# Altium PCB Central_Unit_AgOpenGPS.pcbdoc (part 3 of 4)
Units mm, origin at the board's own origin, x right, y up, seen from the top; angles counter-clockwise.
Board outline 200.19 x 122.57 mm, 2 copper layers (Top Layer, Bottom Layer); 271 components, 213 nets, 1023 pads, 412 vias.
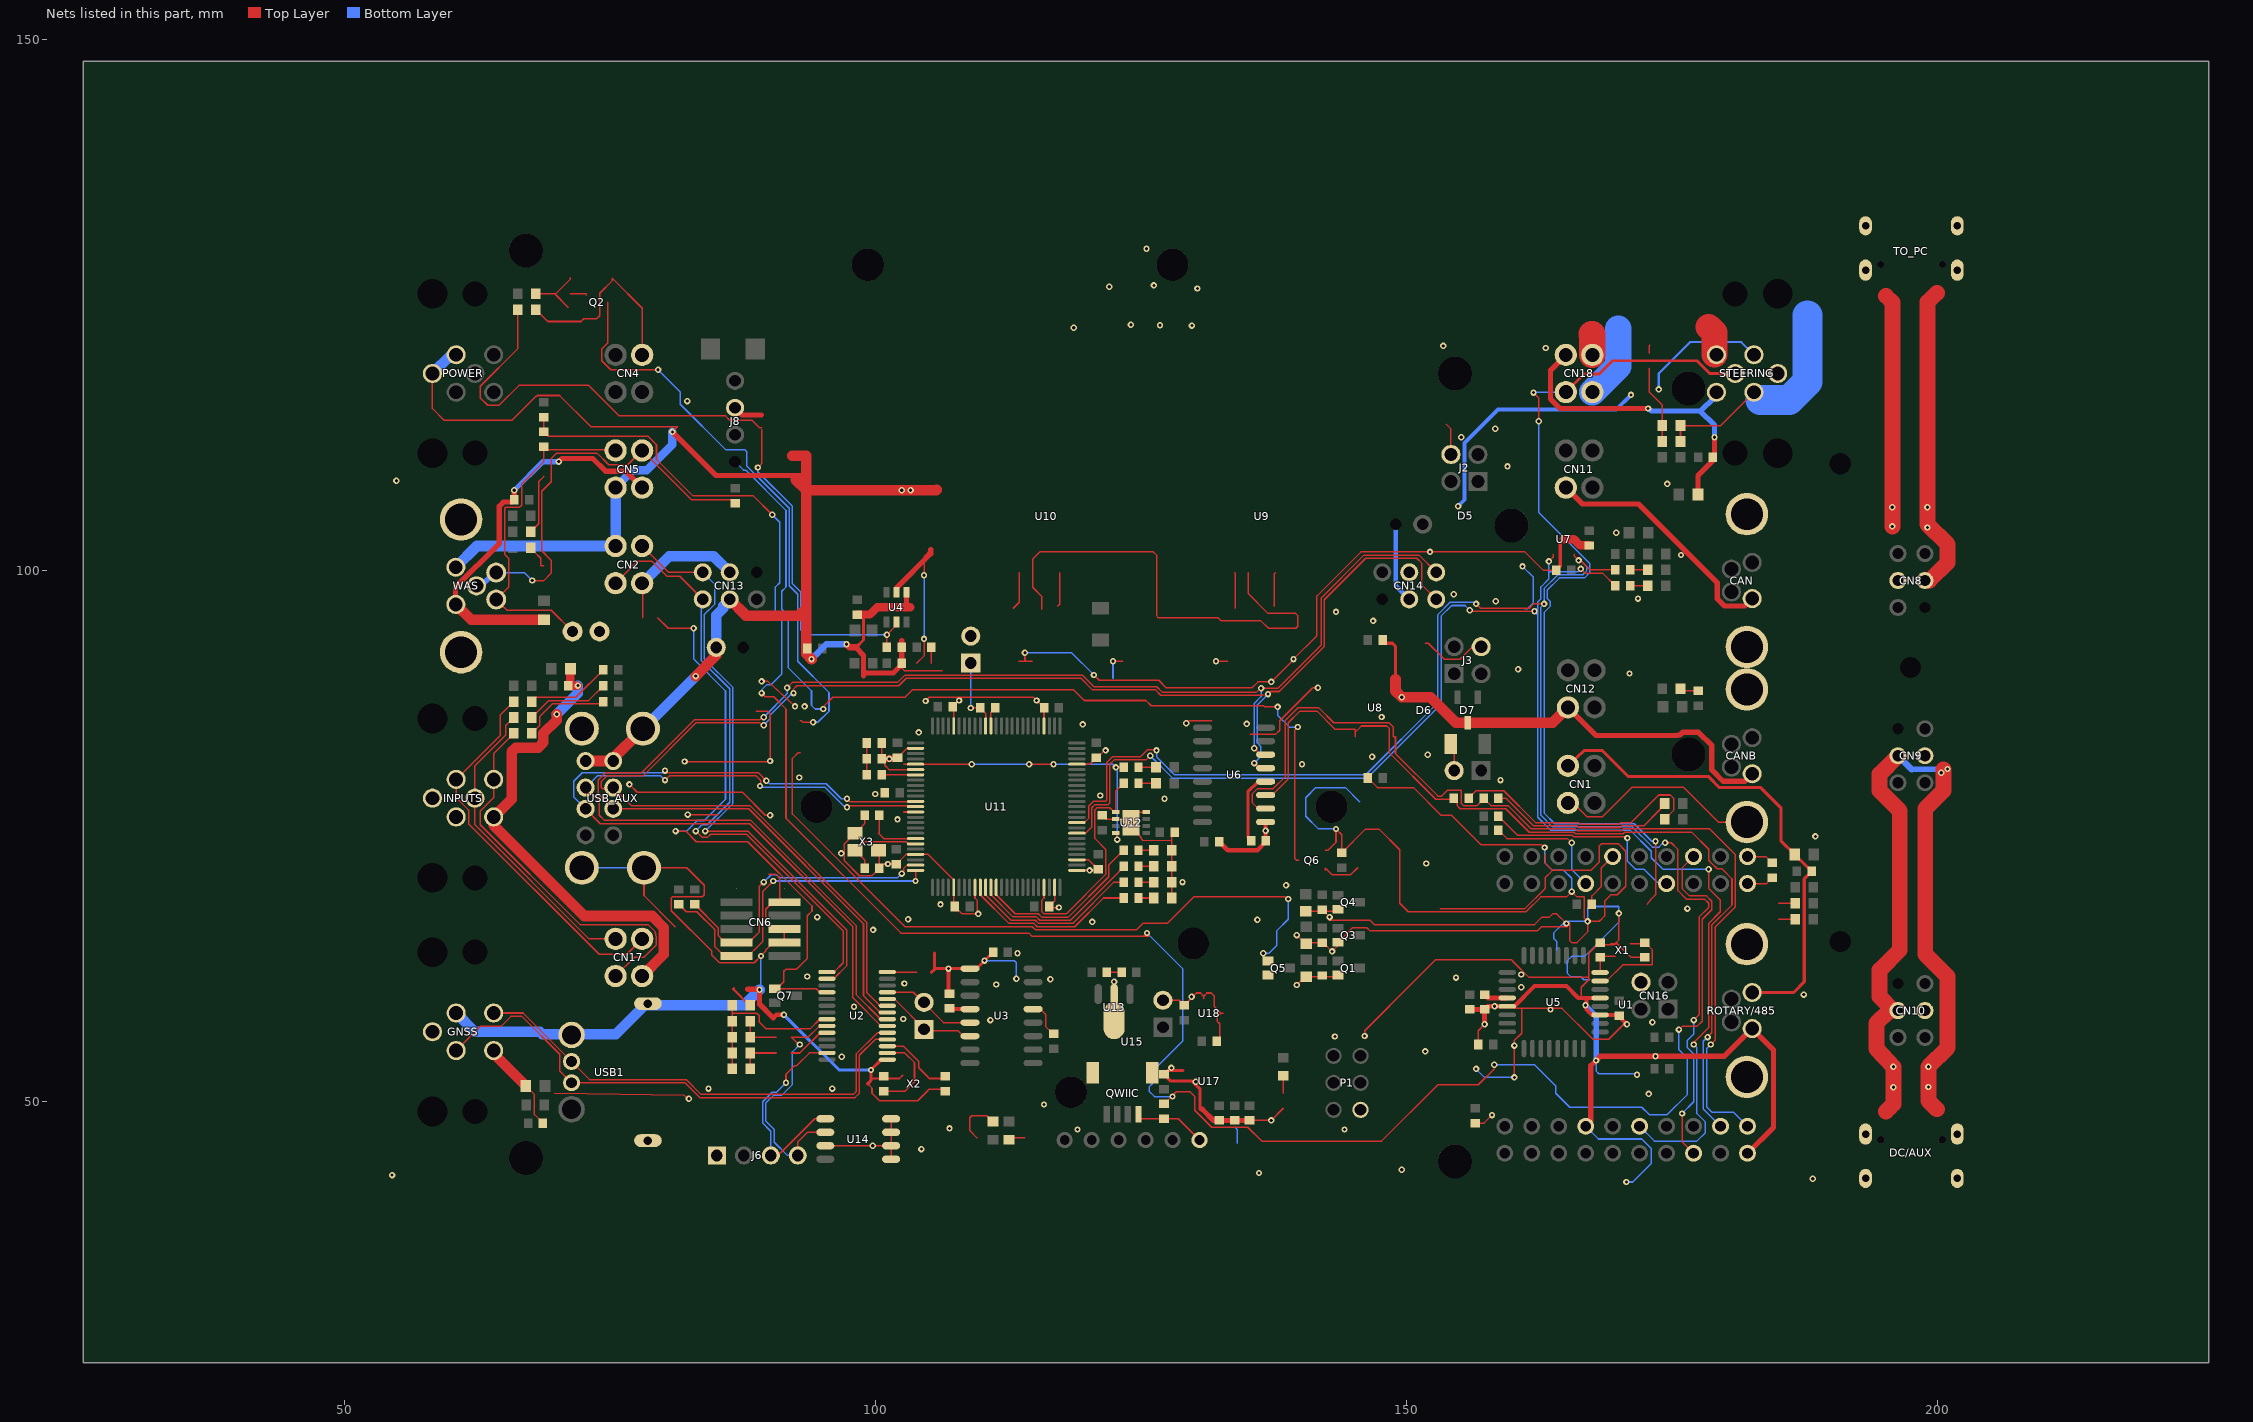
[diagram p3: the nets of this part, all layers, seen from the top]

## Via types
v1: diameter 0.6, hole 0.3, Top Layer to Bottom Layer, 411 vias
v2: diameter 0.61, hole 0.305, Top Layer to Bottom Layer, 1 vias

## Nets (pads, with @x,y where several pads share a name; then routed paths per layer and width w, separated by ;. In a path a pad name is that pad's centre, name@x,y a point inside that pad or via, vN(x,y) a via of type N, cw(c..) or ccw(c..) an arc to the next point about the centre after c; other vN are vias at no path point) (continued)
GND: 12V.1 BOOT.2 C1.1 C2.2 C3.2 C4.2 C5.1 C6.1 C8.1 C9.1 C10.1 C11.2 C12.1 C13.1 C14.2 C15.2 C17.1 C18.1 C19.1 C20.1 C21.1 C22.2 C23.2 C24.1 C25.1 C26.2 C27.1 C28.1 C29.1 C32.2 C33.1 C34.2 C35.2 C36.2 C37.1 C38.2 C39.1 C40.2 C41.1 C42.1 C43.1 C44.1 C45.1 C46.1 C47.1 C48.1 C49.1 C50.1 C51.1 C52.2 C53.2 C54.1 C55.1 C56.2 C57.1 CAN.3 CAN.Shield CANB.3 CANB.Shield CN1.3 CN2.4 CN4.3 CN5.2 CN6.3 CN6.5 CN6.9 CN7.2 CN11.3 CN12.3 CN13.4 CN14.4 CN15.2 CN16.4 D2.2 D5.3 D6.3 D7.3 GNSS.4 GNSS.Shield INPUTS.3 INPUTS.Shield J5.2 J6.1 LED1.1 LED2.1 LED3.1 LED4.1 P1.6 POWER.3 POWER.Shield Q1.2 Q3.2 Q4.2 Q5.2 Q6.2 QWIIC.1 QWIIC.5 QWIIC.6 R1.1 R10.1 R14.1 R16.2 R18.1 R25.2 R26.2 R27.2 R36.1 R38.2 R42.2 R44.1 R47.1 R70.1 R77.2 R81.2 R82.2 R93.2 ROTARY/485.3 ROTARY/485.Shield STEERING.3 STEERING.Shield U1.1 U1.4 U1.27 U2.1 U3.1 U4.1 U5.3 U5.5 U5.21 U6.1 U7.2 U7.8 U7.9 U8.5 U11.2 U11.6 U11.14 U11.22 U11.30 U11.34 U11.49 U11.51 U11.53 U11.71 U11.79 U11.96 U12.2 U12.8 U12.9 U13.2 U14.1 U14.2 U14.3 U14.4 U14.7 U15.6 U17.1 U17.3 U18.5 U18.7 U18.10 U18.12 USB1.0 USB1.4 USB_AUX.4 USB_AUX.8 USB_AUX.9 WAS.3 WAS.Shield X1.2 X1.4 X2.2 X2.4 X3.2 X3.4 | length 1071.3
  Top Layer w0.145: POWER.Shield@58.287,118.566 58.287,115.266 59.387,114.166 65.787,114.166 68.02,116.399 68.05,116.399 68.143,116.493 70.26,116.493 73.187,113.566 81.387,113.566 v1(80.887,113.066) ; 12V.1@68.037,124.566 69.139,123.464 72.289,123.464 72.541,123.716 73.737,123.716 74.037,124.016 74.037,126.116 75.237,127.316 75.237,127.516 78.037,124.716 CN4.3@78.037,120.316 ; 69.787,50.766 81.987,50.566 v1(82.437,50.266) ; v1(76.837,79.866) 77.587,79.116 87.487,79.116 89.637,76.966 v1(90.087,76.966) ; USB_AUX.9@78.211,72.015 78.211,69.392 81.137,66.466 ; USB_AUX.9@78.212,72.017 82.238,72.017 83.887,70.366 83.887,69.467 83.688,69.266 80.887,69.266 80.788,69.167 80.788,67.965 84.588,64.166 84.588,63.785 85.245,63.129 85.387,63.066 88.588,63.066 v1(89.228,63.706) 89.688,64.166 89.688,64.267 90.381,64.961 CN6.3@91.437,64.961 CN6.5@91.437,66.231 ; v1(82.037,82.016) 90.037,82.016 v1(90.087,82.066) 90.087,86.568 89.889,86.766 88.786,86.766 ; v1(82.337,77.016) 85.187,77.016 ; v1(89.287,89.566) 89.887,89.566 v1@92.436,87.216 ; 89.987,71.416 90.587,71.416 90.987,71.016 90.987,69.221 CN6.9@91.437,68.771 90.343,68.771 89.688,68.115 89.688,66.767 90.221,66.231 CN6.5@91.437,66.231 ; CN6.5@90.252,66.231 CN6.5@91.437,66.231 ; U14.7@95.287,45.831 99.752,45.831 U14.2@101.487,45.831 ; X3.2@98.087,75.266 97.087,74.265 97.087,72.667 98.489,71.265 99.685,71.265 C39.1@100.387,71.966 ; X3.2@98.087,75.266 98.987,76.166 C37.1@98.987,76.966 ; C12.1@99.287,51.666 99.688,51.265 99.688,50.767 100.386,50.066 103.988,50.066 X2.2@104.787,50.866 ; X3.4@100.287,73.666 100.387,73.566 C39.1@100.387,71.966 100.787,72.366 C51.1@101.987,72.366 102.887,73.266 U11.22@103.787,73.266 104.987,73.266 107.387,70.866 U11.30@107.387,70.166 107.387,68.466 C54.1@107.487,68.366 ; R82.2@100.587,82.266 100.887,82.266 100.887,81.666 101.288,81.265 U11.6@103.787,81.265 ; R82.2@100.587,82.266 R81.2@100.587,83.766 ; U14.1@101.487,44.561 U14.4@101.487,48.371 ; C47.1@102.087,82.366 102.987,83.266 U11.2@103.787,83.266 ; R70.1@102.487,91.266 102.487,90.816 102.737,90.566 106.287,90.566 ; 102.687,77.266 U11.14@103.787,77.266 ; v1(104.737,87.716) 105.087,88.066 108.48,88.066 ; U11.96@107.387,85.366 107.387,87.066 C46.1@107.287,87.166 108.187,88.066 114.887,88.066 C43.1@115.887,87.066 U11.79@115.887,85.366 ; C54.1@107.487,68.366 108.187,67.666 109.487,67.666 109.586,67.767 109.586,68.966 109.388,69.167 U11.34@109.387,70.166 ; R26.2@113.487,91.466 R42.2@114.787,91.466 ; v1(114.087,92.266) 114.097,91.465 ; U11.49@116.887,70.166 116.887,68.866 C50.1@116.387,68.366 116.487,68.266 v1(117.287,68.266) ; U11.51@118.987,71.766 v1(120.185,71.766) 120.887,71.766 C41.1@120.987,71.866 120.087,72.766 U11.53@118.987,72.766 ; U11.71@118.987,81.766 120.187,81.766 C42.1@120.787,82.366 ; v1(120.587,90.166) 121.087,89.666 126.688,89.667 127.387,88.966 135.489,88.966 136.038,89.515 v1(137.287,89.516) 139.387,91.615 v1(139.387,91.666) 141.587,93.866 141.587,97.616 145.737,101.766 v1(152.237,101.766) ; C42.1@120.787,82.366 120.887,82.367 121.588,83.066 v1(121.687,83.066) ; C40.2@121.387,76.966 121.757,76.596 U12.2@122.655,76.596 123.757,76.596 v1(124.087,76.266) ; C53.2@121.787,62.166 C52.2@123.187,62.166 ; v1(122.387,91.466) R25.2@123.287,91.466 ; QWIIC.1@124.787,48.816 124.788,48.367 127.186,48.367 128.537,48.367 130.137,46.767 U15.6@130.386,46.767 ; U12.8@125.52,77.257 124.087,77.257 v1(124.087,76.266) ; CN15.2@127.087,59.536 128.617,59.536 C15.2@129.087,59.066 ; LED1.1@127.937,69.166 127.937,75.116 C45.1@128.187,75.366 ; 127.937,74.606 125.187,74.566 v1(124.087,76.266) ; C15.2@129.086,59.065 130.236,60.216 130.638,60.216 130.94,59.914 U18.12@130.939,59.667 ; v1(129.287,85.616) 129.537,85.866 131.687,85.866 ; 130.94,59.804 130.94,59.919 131.237,60.216 131.639,60.216 131.938,59.914 131.938,59.667 ; U18.10@131.939,59.667 131.939,58.914 132.537,58.317 ; v1(132.087,91.466) R27.2@133.187,91.466 ; C8.1@132.137,55.666 132.439,55.968 132.439,56.967 132.439,57.314 132.187,57.566 132.187,57.967 132.537,58.317 ; U18.7@132.789,58.317 132.537,58.317 ; C25.1@135.239,48.217 v1(137.287,48.217) R10.1@138.429,49.358 ; 135.337,84.567 137.686,84.567 138.088,84.966 138.088,85.865 141.189,88.966 v1(141.687,88.966) ; v1(139.687,60.966) 140.587,61.867 R44.1@140.587,62.065 ; v1(139.687,65.666) 140.286,65.067 R47.1@140.587,65.067 ; R36.1@140.53,67.915 143.381,67.915 Q4.2@143.571,68.106 ; R44.1@140.587,61.766 143.432,61.766 Q1.2@143.571,61.906 ; R47.1@140.587,65.066 140.687,64.966 C29.1@142.087,64.966 142.187,64.966 v1(143.019,64.135) 143.571,64.687 Q3.2@143.571,65.006 ; C27.1@142.087,68.066 v1(142.787,67.366) ; Q6.2@142.387,73.666 142.637,73.665 143.389,74.417 v1(143.387,75.666) ; v1(142.787,67.366) 142.787,67.066 146.586,67.066 146.988,66.665 162.086,66.665 162.787,67.366 163.488,67.366 163.787,67.666 164.189,67.666 v1(165.087,66.766) ; v1(143.387,75.666) 143.937,75.116 R77.2@143.937,73.416 146.177,75.656 147.447,75.656 149.388,73.715 149.388,68.666 150.188,67.866 161.288,67.866 162.687,69.266 165.088,69.266 v1(165.587,69.766) 166.087,69.266 166.787,69.266 166.787,67.266 v1(167.087,66.966) 168.187,66.966 168.287,67.066 168.316,67.097 168.687,67.465 168.687,68.867 169.286,69.467 169.888,69.467 170.688,70.267 170.688,73.564 169.988,74.267 168.387,74.267 168.187,74.066 168.187,72.565 167.386,71.765 163.787,71.765 ; Q3.2@143.571,65.006 144.933,66.365 146.287,66.365 146.589,66.065 162.337,66.065 162.738,66.467 165.187,66.467 165.187,66.767 164.788,66.767 165.388,66.767 165.388,65.166 165.588,64.966 166.086,64.966 167.087,65.966 v1@167.087,66.965 ; v1(146.087,56.166) 146.087,56.666 150.887,61.466 152.787,63.366 153.987,63.366 159.887,63.366 160.187,63.066 161.532,61.721 167.188,61.721 ; R93.2@146.387,80.466 147.29,79.563 150.691,79.563 153.287,76.967 154.267,76.967 156.886,74.346 ; v1(152.237,101.766) 161.186,101.765 162.936,100.015 C2.2@164.137,100.016 ; 153.187,68.166 161.186,68.166 163.086,70.066 163.086,71.067 163.787,71.765 ; C56.2@156.487,47.966 157.337,47.966 v1(158.087,48.716) ; C57.1@156.787,55.366 156.787,56.666 v1(157.387,57.266) ; 156.815,74.417 157.066,74.166 162.787,74.166 v1(163.037,73.916) ; U5.21@159.518,58.966 160.188,58.966 160.188,58.766 164.686,58.766 167.587,55.865 169.088,55.865 170.488,57.267 v1(170.787,57.266) ; v1(160.187,52.266) v1(160.187,55.266) 160.188,55.738 160.887,56.436 160.887,58.766 163.488,58.766 v1(163.587,58.666) ; 163.086,73.266 163.086,72.466 163.787,71.765 ; 164.829,71.765 163.787,71.765 ; CN1.3@165.237,78.116 165.738,78.115 167.036,76.815 168.486,76.815 171.287,79.616 176.087,79.616 179.387,76.316 CANB.Shield@182.087,76.316 ; C5.1@167.987,64.766 169.587,64.766 X1.4@169.687,64.866 170.037,65.216 v1(170.037,67.716) ; C5.1@167.988,64.765 167.188,63.967 167.188,61.468 166.487,60.767 166.487,59.746 U5.5@168.255,59.746 ; 169.287,64.866 169.887,64.866 X1.2@171.087,63.666 171.187,63.566 C6.1@172.487,63.566 ; U1.1@182.147,73.066 183.887,73.066 C55.1@184.487,72.466
  Top Layer w0.15: C12.1@99.287,51.666 99.787,52.166 100.787,52.166 102.287,52.166 X2.4@102.587,52.466 ; X2.2@104.787,50.866 105.087,51.166 C23.2@106.387,51.166
  Top Layer w0.3: R18.1@98.187,92.766 98.887,93.466 98.887,95.867 ; C19.1@98.286,95.867 98.786,95.867 98.987,95.667 ; C12.1@99.287,51.666 99.587,51.966 v1(99.587,52.966) 100.56,53.939 U2.1@101.132,53.938 ; C10.1@105.587,63.966 105.587,62.466 R1.1@105.287,62.166 105.632,62.511 v1(106.897,62.511) U3.1@108.915,62.511 109.532,62.511 v1(110.287,63.266) C35.2@111.087,64.066 ; U17.3@128.988,51.917 129.836,51.917 130.587,51.166 130.587,49.266 ; U17.1@128.988,52.917 127.538,52.917 C9.1@127.187,52.566 127.837,51.916 129.837,51.916 ; C36.2@147.787,93.466 148.088,93.165 148.687,93.165 148.992,92.86 U8.5@148.992,89.786 ; C2.2@164.137,100.016 164.507,100.386 U7.2@164.507,101.533 ; 164.507,100.983 164.507,102.636 U7.9@164.837,102.966
  Top Layer w0.4: 90.387,57.866 90.687,58.166 v1(91.387,58.166) ; v1(106.897,62.511) 106.897,60.256 C1.1@106.987,60.166 ; C4.2@132.387,74.466 133.188,73.665 135.987,73.665 136.759,74.437 v1@136.759,75.26 ; U6.1@136.759,76.321 v1(136.759,75.492) 136.759,74.594 C38.2@136.787,74.566 ; U5.21@159.518,58.96 160.181,58.959 162.087,60.866 165.087,60.866 166.207,59.746 166.988,59.746 ; U5.3@168.255,58.148 167.503,58.148 166.988,58.666 166.988,59.746 ; U5.5@168.255,59.746 166.988,59.746 ; U5.3@168.256,58.149 169.904,58.149 v1(170.787,57.266)
  Top Layer w0.45: C22.2@155.987,58.666 157.187,58.666 C3.2@157.287,58.566 ; v1(157.387,57.266) 157.387,58.566 C3.2@157.287,58.566 ; U5.21@159.518,58.966 v1(158.324,58.962) 157.681,58.959 C3.2@157.287,58.566
  Top Layer w0.5: v1(80.887,113.066) 84.987,108.966 93.487,108.966 ; R14.1@87.987,60.566 89.038,60.566 v1(89.087,60.516) 89.087,59.166 90.387,57.866 ; R18.1@98.187,92.766 98.887,92.016 98.887,90.066 ; 98.888,90.665 98.888,90.566 99.086,90.366 101.687,90.366 102.487,91.166 102.487,93.416 102.487,93.366 ; U4.1@102.937,97.966 102.937,96.616 102.987,96.566 ; 130.788,49.266 131.837,48.217 C25.1@135.239,48.217 ; CN11.3@165.037,107.816 166.588,106.266 171.887,106.266 179.287,98.866 179.287,97.366 179.987,96.666 181.887,96.666 CAN.3@182.587,97.366 ; CN12.3@165.237,87.116 167.887,84.466 175.527,84.466 175.577,84.516 175.787,84.516 176.037,84.766 177.537,84.766 178.787,83.516 178.787,81.216 179.837,80.166 181.888,80.166 CANB.3@182.587,80.866 ; U1.27@166.907,47.666 167.387,48.146 167.387,53.366 168.287,54.266 179.987,54.266 ROTARY/485.3@182.587,56.866 184.587,54.866 184.587,47.566 U1.4@182.147,45.126
  Top Layer w0.6: v1(97.287,93.066) 97.587,92.766 R18.1@98.187,92.766 ; R82.2@100.587,82.266 v1(101.312,82.266) 101.987,82.266 C47.1@102.087,82.366
  Top Layer w0.8: C19.1@98.287,95.866 99.487,95.867 100.188,96.566 103.287,96.566 ; 164.836,102.967 165.784,102.969 166.386,102.367 C48.1@167.237,102.366
  Top Layer w1: USB_AUX.4@72.712,82.066 75.061,82.066 USB_AUX.9@78.112,85.117 ; v1(83.087,90.066) 85.017,92.022 CN7.2@85.017,92.766 ; CN13.4@86.287,97.296 87.817,95.766 92.787,95.766 93.387,96.366 C18.1@93.487,96.366 ; C32.2@92.187,110.816 93.488,110.815 93.488,92.167 v1(93.987,91.666) ; 92.487,108.566 93.487,107.566 v1(102.487,107.566) v1(103.325,107.566) 105.722,107.566 D2.2@105.787,107.631 ; U8.5@148.992,89.786 148.992,88.661 v1(149.586,88.067) 152.286,88.067 154.686,85.667 155.786,85.667 163.787,85.667 CN12.3@165.237,87.116
  Bottom Layer w0.145: USB_AUX.9@72.361,72.015 USB_AUX.9@78.211,72.015 ; v1(89.087,60.516) 89.228,60.657 v1(89.228,63.706) ; v1(110.287,63.266) 113.087,63.266 113.287,63.066 v1(113.287,61.566) ; v1(114.087,92.266) 118.487,92.266 v1(120.587,90.166) ; 122.387,89.866 v1(122.387,91.466) ; v1@143.386,75.667 141.738,75.667 140.536,76.866 140.536,78.616 141.486,79.566 144.288,79.566 145.636,78.217 ; v1(156.587,53.066) 157.387,52.266 v1(160.187,52.266) ; v1(160.957,100.397) 161.987,99.366 161.987,96.966 161.437,96.416 161.187,96.416 ; v1(163.037,73.916) 163.037,72.516 163.787,71.766 164.837,71.766 165.587,71.016 v1(165.587,69.766) ; 164.186,64.267 164.186,65.065 163.886,65.367 163.886,65.865 v1@164.788,66.767 ; U1.27@166.907,47.666 168.107,46.466 172.187,46.466 173.087,45.566 173.087,44.166 171.337,42.416 v1(170.737,42.416) ; 167.287,61.466 166.734,61.466 166.434,61.765 165.487,61.765 165.187,62.065 165.187,63.266 165.588,63.665 166.787,63.665 170.038,66.916 v1(170.037,67.716) 170.037,68.366 167.287,68.366 167.087,68.166 v1(167.087,66.966) 165.287,66.966 v1(165.087,66.766) ; v1(167.887,53.866) 167.887,52.865 168.138,52.616 171.636,52.616 v1(171.737,52.516) ; v1@164.787,66.766 v1(165.087,66.766) ; v1@164.788,66.767 v1(165.087,66.766)
  Bottom Layer w0.15: 133.887,47.566 134.087,47.366 134.087,46.066
  Bottom Layer w0.2: v1(173.787,117.066) 173.787,118.566 176.737,121.516 181.574,121.516 STEERING.3@182.755,120.334
  Bottom Layer w0.3: v1(91.387,58.166) 96.587,52.966 v1(99.587,52.966)
  Bottom Layer w0.35: v1(154.887,106.066) 155.487,106.666 155.487,112.012 158.641,115.166 162.421,115.166 ; 159.187,115.166 158.787,115.166 169.787,115.166 v1(171.172,116.551)
  Bottom Layer w0.5: v1(166.887,59.066) 167.887,58.066 v1(167.887,53.866)
  Bottom Layer w0.6: v1(93.987,91.666) 95.387,93.066 v1(97.287,93.066)
  Bottom Layer w0.8: CN5.2@75.537,107.816 77.189,109.466 78.486,109.466 80.887,111.867 v1(80.887,113.066)
  Bottom Layer w1: POWER.Shield@58.287,118.566 60.055,120.334 POWER.3@60.519,120.334 ; WAS.3@60.487,100.316 62.487,102.316 CN2.4@75.537,102.317 CN5.2@75.537,107.816 ; GNSS.4@60.519,58.334 62.286,56.566 68.387,56.566 68.636,56.317 75.538,56.317 78.287,59.066 87.638,59.066 v1(89.087,60.516) ; USB_AUX.9@78.112,85.117 78.138,85.117 v1(83.087,90.066) ; CN7.2@85.017,92.766 85.017,95.796 85.687,96.466 85.687,96.696 CN13.4@86.287,97.296
  other v1: 188.287,42.716 54.487,43.066 136.137,43.266 149.587,43.566 104.337,45.516 99.752,45.831 119.037,47.366 144.187,47.366 106.987,47.466 115.887,49.716 172.837,50.716 84.287,51.216 95.937,51.216 130.187,51.866 127.887,53.166 96.837,54.216 173.487,54.266 151.787,54.716 143.287,56.116 173.187,57.466 110.837,57.666 102.637,57.766 97.987,58.916 129.787,59.866 187.437,60.066 160.837,60.766 111.387,61.016 102.737,61.116 122.487,61.279 116.487,61.516 154.687,61.666 93.587,61.766 160.837,61.966 113.387,63.966 99.787,66.166 120.437,66.916 135.987,67.116 103.087,67.166 94.537,67.366 109.687,67.666 176.487,68.166 106.137,68.566 138.687,70.366 128.937,70.666 101.187,72.366 151.887,72.416 96.787,73.366 188.537,74.966 102.087,76.566 127.237,78.516 121.187,78.816 99.987,78.966 158.887,80.266 92.837,80.516 140.187,81.766 146.787,82.466 152.037,82.666 104.087,84.766 119.537,85.516 134.987,85.566 147.687,86.216 92.437,87.216 93.337,87.216 107.887,87.766 115.187,87.766 171.037,90.316 160.537,90.716 146.887,95.266 143.387,96.116 158.437,97.116 171.837,97.366 154.487,97.766 175.887,101.466 169.787,103.566 174.587,108.166 54.887,108.466 159.537,109.816 155.187,112.566 158.387,113.366 82.287,115.966 163.137,120.966 153.487,121.166
GND1: CN8.4 TO_PC.1 TO_PC.2 TO_PC.3 TO_PC.4 TO_PC.A1 TO_PC.A12 TO_PC.B1 TO_PC.B12
GND2: CN9.4 CN10.4 DC/AUX.1 DC/AUX.2 DC/AUX.3 DC/AUX.4 DC/AUX.A1 DC/AUX.A12 DC/AUX.B1 DC/AUX.B12
GNSS+: F1.1 GNSS.2 R64.2 | length 8.8
  Top Layer w0.145: F1.1@67.087,51.466 67.887,50.665 67.887,48.766 R64.2@68.687,47.966
  Top Layer w1: GNSS.2@64.055,54.798 64.055,54.498 F1.1@67.087,51.466
IN0: CN17.4 INPUTS.5 STEER.2 | length 29.3
  Top Layer w0.145: STEER.2@65.936,86.167 65.187,85.415 65.187,84.516 62.286,81.615 62.286,78.567 62.286,76.065 73.036,65.316 CN17.4@75.537,65.316
IN1: CN17.2 INPUTS.1 WORK.2 | length 36.9
  Top Layer w0.145: WORK.2@65.936,84.666 64.054,82.784 64.054,80.335 64.054,78.633 62.787,77.366 62.787,76.065 72.187,66.665 78.588,66.665 79.287,65.966 79.363,65.481 79.363,64.742 78.187,63.566 77.288,63.566 CN17.2@75.537,61.816
IN2: CN17.3 INPUTS.4 REMOTE.2 | length 36.3
  Top Layer w0.145: REMOTE.2@65.936,87.666 64.687,86.416 64.687,84.503 INPUTS.4@60.519,80.334 60.519,78.633 61.687,77.465 61.687,76.167 73.988,63.866 76.587,63.866 CN17.3@78.037,65.316
IN+: CN17.1 F4.2 INPUTS.2 R73.2 | length 45.8
  Top Layer w0.8: R73.2@71.087,89.166 v1(71.987,89.166) ; R73.2@71.087,89.166 71.288,89.167 F4.2@71.287,90.766
  Top Layer w1: v1(69.987,86.466) 69.988,85.916 68.738,84.668 68.738,83.818 68.238,83.317 66.137,83.317 65.738,82.916 65.738,78.481 64.054,76.797 64.054,75.999 72.586,67.465 78.987,67.465 80.087,66.365 80.087,63.866 CN17.1@78.037,61.816
  Bottom Layer w1: v1(69.987,86.466) 71.987,88.466 v1(71.987,89.166)
INH: R61.2 U9.3 U10.3 | length 45.2
  Top Layer w0.145: U10.3@114.817,99.782 114.817,101.096 115.487,101.766 126.187,101.766 126.487,101.466 126.487,95.764 126.62,95.565 132.286,95.565 132.586,95.265 136.322,95.265 137.023,94.567 139.589,94.567 139.787,94.765 139.787,95.766 139.586,95.966 136.988,95.966 135.118,97.836 U9.3@135.117,99.782
  Top Layer w0.15: 114.816,99.781 114.816,98.435 115.687,97.566 115.687,96.366
J1_1: CN14.3 J1.1 | length 7.6
  Bottom Layer w0.45: J1.1@149.017,104.366 149.017,98.567 CN14.3@150.287,97.296
J2_4: J2.4 R60.2 | length 3
  Top Layer w0.145: R60.2@153.787,113.766 154.217,113.336 J2.4@154.217,110.936
J4_2: J4.2 R92.1 | length 2.6
  Top Layer w0.145: R92.1@154.187,83.666 154.517,83.336 J4.2@154.517,81.166
J8_3: J8.3 R15.2 | length 2.8
  Top Layer w0.5: J8.3@86.787,115.336 87.457,114.666 R15.2@89.287,114.666
LED1_2: LED1.2 R84.1 | length 1.5
  Top Layer w0.145: R84.1@124.787,69.166 LED1.2@126.237,69.166
LED2_2: LED2.2 R85.1 | length 1.5
  Top Layer w0.145: R85.1@124.787,70.666 LED2.2@126.237,70.666
MA: CN18.4 M1.2 M2.1 STEERING.4 STEERING.@180.987,126.066 STEERING.@184.987,126.066 U10.8 | length 28.1
  Top Layer w0.145: M1.2@175.837,112.166 M2.1@175.837,113.666 ; M2.1@175.837,113.666 179.623,113.666 STEERING.4@182.755,116.798
  Bottom Layer w2.5: CN18.4@167.536,116.815 169.987,119.266 169.987,122.766
  Bottom Layer w2.8: 183.337,116.066 186.086,116.066 187.806,117.785 187.806,124.044
  other v1: 129.812,123.077 126.815,123.102 124.072,123.153 130.337,126.566 122.04,126.735 126.237,126.866 125.537,130.316
  other v2: 118.687,122.866
MB: CN18.2 R24.2 STEERING.2 U9.4 U9.8 | length 5.6
  Top Layer w0.145: R24.2@172.887,120.466 172.887,121.166 172.937,121.216
  Top Layer w2.45: 178.487,122.966 179.019,122.434 STEERING.2@179.019,120.334
  Top Layer w2.5: 167.488,122.266 167.536,122.266 CN18.2@167.536,120.315
OUT: J8.1 Q6.3 | length 89.5
  Top Layer w0.145: v1(95.087,86.966) 95.086,86.965 94.986,86.965 94.986,87.066 95.985,88.067 102.787,88.067 103.488,88.765 118.687,88.765 119.685,87.767 125.487,87.767 125.987,87.267 136.388,87.267 ; 135.158,87.267 136.545,87.267 136.646,87.166 v1(137.887,87.166) ; v1(139.787,85.266) 139.487,84.966 139.487,72.916 139.688,72.715 Q6.3@139.888,72.716
  Bottom Layer w0.145: 86.998,110.256 J8.1@86.787,110.256 87.577,109.466 87.788,109.466 91.588,105.667 91.588,98.466 91.186,98.067 91.186,96.368 91.786,95.768 91.786,90.866 93.988,88.664 93.988,87.307 94.328,86.967 v1@94.986,86.967 ; v1(137.887,87.166) 137.887,86.386 139.007,85.266 v1(139.787,85.266)
R3_2: AUX0.1 GNSS_.2 R3.2 | length 4.8
  Top Layer w0.15: AUX0.1@88.237,53.073 GNSS_.2@88.237,54.566 ; R3.2@90.687,54.566 GNSS_.2@88.237,54.566 ; GNSS_.2@88.237,54.566 87.937,54.866 GNSS_.2@88.237,54.566
R4_1: ARDU.1 AUX1.2 R4.1 | length 4
  Top Layer w0.15: ARDU.1@88.237,57.566 AUX1.2@88.237,56.066 R4.1@90.687,56.066
R8_2: Q2.1 R8.2 | length 1.6
  Top Layer w0.145: R8.2@71.287,126.066 72.771,126.066 Q2.1@72.771,125.926
R10_2: LED.2 R10.2 | length 1.6
  Top Layer w0.145: R10.2@138.429,50.758 LED.2@138.43,52.409
R14_2: R14.2 USB:.1 | length 2.4
  Top Layer w0.2: R14.2@86.587,60.566 86.688,60.665 86.688,60.516 88.136,59.065 USB:.1@88.237,59.066
R15_1: 12V.2 C44.2 R15.1 U4.5 | length 71.9
  Top Layer w0.145: 12V.2@66.337,124.566 66.338,120.917 62.787,117.366 62.787,116.266 63.488,115.565 64.555,115.565 66.432,117.442 73.013,117.442 75.888,114.567 85.888,114.567 86.287,114.165 88.387,114.165 89.086,113.467 89.287,113.467 ; v1(88.937,109.716) 89.287,110.066 R15.1@89.287,113.266 ; v1(101.087,93.966) C44.2@101.087,92.766 101.087,93.967 101.987,94.867 U4.5@101.987,95.166
  Bottom Layer w0.145: v1@88.936,109.715 88.936,109.317 92.187,106.065 92.187,98.765 92.987,97.965 92.987,94.366 93.389,93.965 v1(101.087,93.966)
R19_2: C16.2 R19.2 | length 1.5
  Top Layer w0.145: R19.2@105.287,91.266 C16.2@105.287,92.766
R22_1: R22.1 TXD.2 | length 4.7
  Top Layer w0.145: R22.1@109.587,46.566 108.887,47.266 108.887,48.466 109.087,48.666 110.487,48.666 111.037,48.116 TXD.2@111.087,48.116
R23_1: R23.1 RXD.2 | length 1.6
  Top Layer w0.145: RXD.2@112.587,46.416 112.737,46.566 R23.1@114.087,46.566
R24_1: M1.1 M2.2 R24.1 | length 7.4
  Top Layer w0.145: R24.1@172.887,119.066 172.887,116.816 174.137,115.566 M1.1@174.137,112.166
R31_2: CHB.1 R31.2 | length 1.5
  Top Layer w0.145: R31.2@185.087,67.166 CHB.1@186.637,67.166
R32_2: CHA.1 R32.2 | length 1.5
  Top Layer w0.145: R32.2@185.087,68.666 CHA.1@186.637,68.666
R33_1: Q6.1 R33.1 | length 3.8
  Top Layer w0.145: Q6.1@142.387,71.766 142.388,71.966 142.987,71.366 144.788,71.366 R33.1@145.437,72.016
R50_1: CN2.1 CN13.3 R50.1 | length 13.2
  Top Layer w0.145: CN2.1@78.037,98.816 78.087,98.766 R50.1@78.087,95.566
  Bottom Layer w1: CN2.1@78.037,98.816 80.587,101.366 84.757,101.366 CN13.3@86.287,99.836
R51_1: MOT.1 R8.1 R49.2 R51.1 | length 5.7
  Top Layer w0.145: R8.1@69.887,126.066 71.287,127.466 R51.1@71.287,127.566
  Top Layer w0.15: MOT.1@68.037,126.066 R8.1@69.887,126.066 ; 69.805,126.065 71.084,124.787
R57_2: R57.2 WAS2.1 | length 5.7
  Top Layer w0.145: WAS2.1@67.537,103.666 68.288,104.417 68.287,108.366 68.786,108.867
R58_2: R58.2 WAS1.1 | length 2.6
  Top Layer w0.145: WAS1.1@67.537,102.166 67.887,102.166 67.887,101.765 68.487,101.166 68.487,100.467 68.786,100.467
R59_2: CN18.3 R59.2 STEERING.5 | length 83.8
  Top Layer w0.145: v1(161.987,116.766) 162.487,116.266 v1(162.487,114.066) ; R59.2@172.687,68.566 173.086,69.065 173.188,69.167 173.487,69.466 v1(173.487,74.516)
  Top Layer w0.28: CN18.3@165.037,116.815 166.736,118.516 168.187,118.516 169.436,119.766 177.386,119.766 178.588,118.567 STEERING.5@180.987,118.566
  Bottom Layer w0.145: v1(161.987,116.766) 162.036,116.815 CN18.3@165.037,116.815 ; v1(162.487,114.066) 162.487,105.466 167.287,100.665 167.287,99.817 166.787,99.317 164.438,99.317 163.287,98.166 163.287,97.366 163.587,97.066 163.587,96.665 162.987,96.065 162.987,77.165 163.985,76.167 171.486,76.167 173.137,74.516 v1(173.487,74.516)
R63_1: Q2.3 R63.1 | length 54.8
  Top Layer w0.145: Q2.3@74.803,125.266 74.803,121.432 74.237,120.866 74.237,119.766 75.088,118.915 v1(79.537,118.916) ; 92.937,85.866 93.039,85.866 93.189,85.716 v1(94.137,85.716)
  Bottom Layer w0.145: v1(79.537,118.916) 81.636,116.817 81.636,115.667 85.936,111.366 87.724,111.366 87.887,111.204 87.887,109.865 90.188,107.567 ; 89.96,107.794 91.89,105.864 ; 91.89,105.865 91.888,98.565 92.688,97.767 92.688,91.465 95.637,88.517 95.637,86.764 94.588,85.715 v1(94.137,85.716)
R65_2: J3.4 R65.2 | length 6.4
  Top Layer w0.145: R65.2@151.787,93.166 152.087,93.166 153.587,91.666 155.087,91.666 156.257,92.836 J3.4@157.057,92.836
R67_1: R67.1 TX485.1 | length 18.6
  Top Layer w0.145: R67.1@158.687,78.567 159.388,78.567 161.989,75.966 166.086,75.966 166.246,75.806 170.178,75.806 170.338,75.966 172.388,75.966 173.937,77.516 173.937,78.466 TX485.1@174.337,78.066
R69_1: R69.1 TXCAN.1 | length 1.6
  Top Layer w0.145: R69.1@171.087,98.566 TXCAN.1@172.737,98.566
R72_1: FCAN1.2 R72.1 | length 1.7
  Top Layer w0.145: FCAN1.2@175.837,88.866 176.037,88.666 R72.1@177.487,88.666
R80_2: R80.2 R81.1 R82.1 | length 3
  Top Layer w0.145: R80.2@99.187,80.766 R81.1@99.187,83.766
R86_1: LED3.2 R86.1 | length 1.5
  Top Layer w0.145: R86.1@124.787,72.166 LED3.2@126.237,72.166
R87_1: LED4.2 R87.1 | length 1.5
  Top Layer w0.145: R87.1@124.787,73.666 LED4.2@126.237,73.666
R88_1: R88.1 TXCAN1.1 | length 1.6
  Top Layer w0.145: R88.1@124.787,79.966 TXCAN1.1@126.437,79.966
R89_1: R89.1 RXCAN1.1 | length 1.6
  Top Layer w0.145: R89.1@124.787,81.466 RXCAN1.1@126.437,81.466
REMOTE_1: R40.1 REMOTE.1 | length 8
  Top Layer w0.145: REMOTE.1@67.637,87.666 68.037,88.067 71.789,88.067 R40.1@74.387,90.666
ROT+: CN1.1 F6.2 R75.2 ROTARY/485.1 | length 46.1
  Top Layer w0.3: CN1.1@165.237,81.616 166.787,83.066 168.438,83.066 170.887,80.617 178.456,80.617 179.507,79.566 183.388,79.566 185.288,77.666 185.288,74.567 F6.2@186.586,73.266 ; ROTARY/485.1@182.587,60.266 186.487,60.267 187.488,61.267 187.488,70.965 R75.2@188.187,71.666 ; F6.2@186.587,73.266 R75.2@188.187,71.666
RX485_1: R66.1 RX485.1 | length 24.5
  Top Layer w0.145: R66.1@155.887,78.566 156.586,79.266 159.187,79.266 162.187,76.266 166.223,76.266 166.388,76.104 170.01,76.104 170.173,76.266 171.186,76.266 173.787,78.867 174.887,78.867 175.187,78.565 175.187,77.417 RX485.1@174.337,76.566
RXCAN_1: R68.1 RXCAN.1 | length 1.6
  Top Layer w0.145: R68.1@171.087,100.066 RXCAN.1@172.737,100.066
RXD485: R66.2 U1.7 U6.3 U8.1 | length 85.7
  Top Layer w0.145: U6.3@136.759,78.861 137.381,78.862 138.888,80.366 138.888,85.667 139.988,86.766 141.588,86.766 143.287,85.067 145.182,85.067 145.182,84.552 ; U8.1@145.182,84.346 145.182,84.76 145.786,85.367 148.187,85.367 148.387,85.166 148.387,82.865 152.787,78.466 154.486,78.466 154.486,78.565 154.788,78.265 154.788,77.866 155.088,77.567 159.385,77.567 161.585,75.367 165.786,75.367 165.941,75.212 170.434,75.212 170.592,75.369 176.884,75.369 178.486,73.767 178.487,72.716 178.687,72.517 179.286,71.915 179.637,71.916 179.736,71.915 180.686,70.965 180.686,68.517 178.786,66.617 178.786,56.467 v1(178.387,56.066)
  Bottom Layer w0.145: v1(178.387,56.066) 177.988,55.667 177.988,49.284 U1.7@179.606,47.666
RXDCAN: R68.2 U1.12 U7.4 U11.60 | length 142.5
  Top Layer w0.145: U11.60@118.987,76.266 119.688,76.266 120.087,76.665 120.087,77.816 120.536,78.265 121.687,78.265 121.788,78.367 121.788,81.915 122.337,82.466 124.986,82.466 125.639,83.119 126.434,83.119 v1(126.487,83.066) ; v1(156.587,96.866) 156.991,96.466 161.587,96.466 161.987,96.866 v1(162.987,96.866) ; U7.4@165.828,101.533 165.828,101.375 v1(166.237,100.966) ; v1(166.237,100.966) 166.437,100.965 167.338,100.066 R68.2@169.687,100.066 ; v1(174.387,74.366) 174.956,74.366 175.588,73.734 175.588,69.865 176.388,69.065 178.088,69.065 178.486,68.666 178.486,68.265 177.587,67.366 177.587,58.166 v1(177.087,57.666) ; v1(175.987,48.866) 175.987,46.206 U1.12@177.067,45.126
  Bottom Layer w0.145: v1(126.487,83.066) 126.487,82.466 128.187,80.767 146.188,80.767 152.987,87.567 152.987,95.865 154.138,97.015 156.586,97.015 v1(156.587,96.866) ; v1(166.237,100.966) 166.439,100.965 166.988,100.416 166.988,99.967 166.637,99.616 164.288,99.616 162.987,98.316 v1(162.987,96.866) 162.687,96.566 162.687,76.967 163.787,75.865 171.288,75.865 173.188,73.965 173.82,73.965 174.219,74.366 v1(174.387,74.366) ; v1(175.987,48.866) 177.087,49.967 177.087,54.465 176.487,55.065 176.487,55.766 177.087,56.365 v1(177.087,57.666)
RXDCAN1: R89.2 U11.5 U12.4 | length 28.3
  Top Layer w0.145: 102.687,81.766 U11.5@103.787,81.766 108.487,81.766 v1(109.087,81.766) ; v1(114.487,81.766) v1(116.787,81.766) ; U12.4@122.655,75.275 122.787,75.143 v1(122.787,74.666) ; v1(122.655,81.466) R89.2@123.387,81.466
  Bottom Layer w0.145: v1(109.087,81.766) v1(114.487,81.766) ; v1(116.787,81.766) 122.355,81.766 v1(122.655,81.466) 122.787,81.333 v1(122.787,74.666)
S$68: 
S$18375: 
S$55412: 
S$55414: 
S$55416: 
S$55418: 
S$55420: 
S$55422: 
S$55424: 
S$55426: 
S$55428: 
S$55430: 
S$55432: 
S$55434: 
S$55436: 
S$55438: 
S$55440: 
S$55442: 
S$55444: 
S$55446: 
S$55452: 
S$55454: 
S$55456: 
S$55458: 
S$55460: 
S$55462: 
S$55464: 
S$55466: 
S$55468: 
S$55470: 
S$55472: 
S$55474: 
SERVO+: CN18.1 F7.2 R76.1 STEERING.1 | length 30.7
  Top Layer w0.5: CN18.1@165.037,120.316 163.587,118.866 163.587,116.566 163.587,116.166 164.387,115.366 164.487,115.266 168.187,115.266 v1(172.787,115.266) ; F7.2@177.487,107.166 177.488,108.966 179.037,110.515 v1(179.037,112.566)
  Bottom Layer w0.5: v1(172.787,115.266) 173.087,115.066 177.737,115.016 179.02,116.299 STEERING.1@179.02,116.797 ; 177.687,115.016 179.037,113.716 v1(179.037,112.566)
STEER_1: R41.1 STEER.1 | length 8
  Top Layer w0.145: STEER.1@67.637,86.166 69.238,87.765 72.987,87.765 R41.1@74.387,89.166
STEERENABLE: Q5.1 R16.1 R63.2 | length 65.2
  Top Layer w0.145: R63.2@92.937,82.866 92.736,82.865 92.187,82.316 92.187,77.066 102.787,66.467 114.788,66.467 115.085,66.167 124.587,66.167 125.187,66.767 127.488,66.767 129.988,69.266 138.626,69.266 138.827,69.065 v1(138.887,69.066)
  Bottom Layer w0.145: v1(136.537,63.966) 137.088,63.966 137.788,64.666 137.788,66.065 138.888,67.165 v1(138.887,69.066)
SW!: L7.1 R19.1 U4.2 | length 16.6
  Top Layer w0.145: R19.1@103.887,91.266 104.587,91.966 104.587,92.966 v1(104.587,93.566) ; v1(104.587,99.566) 104.587,101.341 L7.1@105.212,101.966
  Top Layer w0.5: U4.2@101.987,97.966 101.987,98.365 105.212,101.591 L7.1@105.212,101.966
  Bottom Layer w0.145: v1(104.587,93.566) v1(104.587,99.566)
SWCLK: CN6.4 R78.2 U11.24 | length 28.7
  Top Layer w0.145: R78.2@82.987,68.566 85.187,66.366 85.187,65.666 85.892,64.961 CN6.4@86.937,64.961 88.082,64.961 88.887,65.766 89.087,65.966 89.087,67.466 89.087,70.266 v1(89.487,70.666) ; v1(102.487,71.466) 102.66,71.638 102.66,71.938 102.987,72.266 U11.24@103.787,72.266
  Bottom Layer w0.145: v1(89.487,70.666) 90.187,71.366 90.687,71.366 90.987,71.066 91.787,71.066 102.087,71.066 v1(102.487,71.466)
SWDIO: CN6.2 R79.2 U11.25 | length 31.9
  Top Layer w0.145: R79.2@81.487,68.566 82.187,67.866 83.187,67.866 84.887,66.166 84.887,64.566 85.762,63.691 CN6.2@86.937,63.691 88.012,63.691 88.987,64.666 89.387,65.066 89.387,67.966 89.387,69.766 v1@90.387,70.766 ; v1(103.787,70.766) U11.25@103.787,71.766
  Bottom Layer w0.145: v1@90.387,70.766 v1(103.787,70.766)
  other v1: 90.387,70.766
TXD485: R67.2 U1.3 U6.2 U8.4 | length 92.9
  Top Layer w0.145: U6.2@136.759,77.591 136.063,77.592 135.487,78.166 135.487,78.966 135.987,79.467 137.488,79.467 138.588,80.566 138.588,85.865 139.787,87.066 141.786,87.066 143.185,85.667 148.385,85.667 148.786,85.265 148.786,84.346 U8.4@148.992,84.346 148.992,82.761 152.987,78.765 153.345,78.765 153.897,79.317 155.136,79.317 155.187,79.266 155.187,78.067 155.388,77.866 156.688,77.866 157.287,78.466 R67.2@157.287,78.567 ; R67.2@157.287,78.566 157.988,77.866 159.586,77.866 161.786,75.667 165.936,75.667 166.094,75.509 170.302,75.509 170.46,75.667 178.585,75.667 180.988,73.264 180.988,68.316 179.088,66.416 179.088,55.766 v1(178.687,55.366)
  Bottom Layer w0.145: v1(178.687,55.366) 178.288,54.966 178.288,49.515 178.837,48.966 180.846,48.966 U1.3@182.146,47.666
TXDCAN: R69.2 U1.19 U7.1 U11.58 | length 147.6
  Top Layer w0.145: U11.58@118.987,75.266 119.787,75.265 120.386,75.865 120.386,77.666 ; 120.384,77.663 120.686,77.965 121.938,77.965 122.088,78.115 122.088,81.765 122.487,82.167 125.487,82.167 v1(125.887,82.566) ; v1(155.987,96.266) 156.086,96.266 156.186,96.166 v1(162.087,96.166) ; v1(163.437,100.866) 163.846,101.275 163.846,101.534 ; v1(166.437,100.166) 166.834,99.769 168.484,99.769 R69.2@169.687,98.566 ; v1(177.087,55.366) 177.087,55.566 178.487,56.966 178.487,66.766 179.587,67.866 179.587,68.966 178.487,70.066 v1(178.487,71.866)
  Bottom Layer w0.145: v1(125.887,82.566) 127.989,80.465 146.338,80.465 153.287,87.417 153.287,95.715 154.288,96.716 155.537,96.716 v1(155.987,96.266) ; 162.388,95.83 162.088,96.13 v1(162.087,96.166) 162.388,96.485 ; 163.437,99.913 166.185,99.913 v1(166.437,100.166) ; v1(163.437,100.866) 163.437,99.215 162.687,98.466 162.687,97.346 162.388,97.046 162.388,76.766 163.589,75.565 171.087,75.565 173.086,73.566 173.086,72.967 174.186,71.867 v1@178.486,71.867 ; U1.19@171.986,47.666 173.386,46.266 177.386,46.266 178.187,47.066 178.187,48.067 177.386,48.867 177.386,55.065 v1(177.087,55.366)
TXDCAN1: R88.2 U11.47 U12.1 | length 21.7
  Top Layer w0.145: U11.47@115.887,70.166 115.888,69.167 115.687,68.966 115.687,67.866 115.888,67.666 117.986,67.666 121.687,71.366 121.687,73.767 120.686,74.765 120.686,77.465 120.887,77.666 122.088,77.666 122.497,77.257 U12.1@122.655,77.257 122.655,79.233 R88.2@123.387,79.966
U1_2: C55.2 U1.2 | length 2.6
  Top Layer w0.145: U1.2@182.147,70.526 183.947,70.526 C55.2@184.487,71.066
U1_14: R96.1 U1.14 | length 19.8
  Top Layer w0.145: R96.1@158.687,76.866 160.485,75.067 165.642,75.067 165.793,74.916 170.737,74.916 v1(170.837,74.816)
  Bottom Layer w0.145: v1@170.836,74.816 170.836,72.619 171.588,71.867 172.388,71.867 173.589,70.665 174.526,70.665 U1.14@174.526,70.526
U1_21: R94.1 U1.21 | length 5.3
  Top Layer w0.145: R94.1@167.487,68.566 167.488,69.365 168.387,70.267 168.387,72.007 U1.21@169.446,73.066
U1_26: R95.1 U1.26 | length 11.8
  Top Layer w0.145: R95.1@158.687,75.566 159.487,74.765 165.187,74.765 v1(165.587,74.366)
  Bottom Layer w0.145: v1(165.587,74.366) 165.587,71.846 U1.26@166.907,70.526
U2_2: C13.2 U2.2 X2.1 | length 8
  Top Layer w0.15: C13.2@100.787,50.966 102.787,50.965 103.687,51.866 103.687,53.666 102.78,54.574 U2.2@101.132,54.573
U2_3: C23.1 U2.3 X2.3 | length 6.9
  Top Layer w0.15: U2.3@101.132,55.208 102.645,55.209 104.087,53.766 104.087,53.166 X2.3@104.787,52.466 105.087,52.166 C23.1@106.387,52.166
U2_14: R1.2 U2.14 | length 2.8
  Top Layer w0.145: U2.14@101.132,62.193 101.16,62.166 R1.2@103.887,62.166
U2_18: Q7.1 R50.2 U2.18 | length 57.9
  Top Layer w0.145: R50.2@79.487,95.566 80.487,94.566 v1(82.887,94.566) ; Q7.1@90.521,60.626 94.428,60.627 94.765,60.29 U2.18@95.442,60.288
  Top Layer w0.15: v1(81.187,75.466) 82.136,75.466 83.137,74.465 87.989,74.465 94.036,68.418 94.036,67.932 93.587,67.483 93.587,63.467 92.586,62.466 91.588,62.466 91.387,62.266 91.387,61.265 90.749,60.626 Q7.1@90.521,60.626
  Bottom Layer w0.15: v1(81.187,75.466) 82.238,75.466 83.236,76.467 83.887,76.467 85.888,78.466 85.888,88.666 82.888,91.666 v1(82.887,94.566)
U2_22: ARDU.2 AUX0.2 AUX1.1 GNSS_.1 U2.22 USB:.2 | length 17.8
  Top Layer w0.15: ARDU.2@86.537,57.566 86.538,58.316 88.837,58.316 89.086,58.067 89.086,57.468 89.688,56.866 93.887,56.866 94.77,57.75 U2.22@95.442,57.748 ; USB:.2@86.537,59.066 AUX0.2@86.537,53.066 ; AUX0.2@86.537,53.066 86.537,53.073 86.838,53.367 AUX0.2@86.537,53.066
U2_24: R3.1 U2.24 | length 4.1
  Top Layer w0.15: R3.1@92.087,54.566 92.888,54.567 94.801,56.48 U2.24@95.442,56.478
U3_4: C1.2 U3.4 | length 2
  Top Layer w0.4: C1.2@106.987,58.766 107.052,58.701 U3.4@108.915,58.701
U3_13: C7.2 U3.13 | length 3.6
  Top Layer w0.145: U3.13@114.859,58.701 115.553,58.702 116.038,58.217 116.037,57.066 C7.2@116.787,56.366
U5_7: C6.2 U5.7 X1.3 | length 9.4
  Top Layer w0.145: U5.7@168.255,61.346 168.867,61.346 170.386,62.865 173.188,62.865 173.188,64.267 C6.2@172.487,64.966 172.388,64.867 X1.3@171.087,64.866
U5_8: C5.2 U5.8 X1.1 | length 3.5
  Top Layer w0.145: U5.8@168.256,62.147 168.256,63.497 167.987,63.766 168.087,63.666 X1.1@169.687,63.666
U5_20: C3.1 U5.20 | length 2.3
  Top Layer w0.45: C3.1@157.387,60.066 157.697,59.756 U5.20@159.518,59.756
U6_4: C38.1 U6.4 | length 6.8
  Top Layer w0.3: C38.1@135.387,74.566 135.087,74.866 135.087,79.166 136.052,80.131 U6.4@136.759,80.131
U9_2: R55.2 U9.2 | length 3.3
  Top Layer w0.15: U9.2@133.847,99.782 133.887,99.742 133.887,96.466
U9_5: R11.2 U9.5 | length 3.1
  Top Layer w0.145: 137.587,96.666 137.587,99.712 U9.5@137.657,99.782
U10_2: R62.1 U10.2 | length 3.5
  Top Layer w0.15: R62.1@112.987,96.466 113.547,97.026 U10.2@113.547,99.782
U10_5: R21.1 U10.5 | length 3.2
  Top Layer w0.15: 117.187,96.666 117.357,96.836 U10.5@117.357,99.782
U11_7: R80.1 U11.7 | length 3.2
  Top Layer w0.145: R80.1@100.587,80.766 U11.7@103.787,80.766
U11_19: C37.2 U11.19 X3.1 | length 5.4
  Top Layer w0.145: C37.2@100.387,76.966 100.387,75.366 X3.1@100.287,75.266 100.787,74.766 U11.19@103.787,74.766
U11_20: C39.2 U11.20 X3.3 | length 8.2
  Top Layer w0.145: C39.2@98.987,71.966 98.987,72.766 X3.3@98.087,73.666 98.887,74.466 102.887,74.466 103.087,74.266 U11.20@103.787,74.266
U11_35: R84.2 U11.35 | length 16.6
  Top Layer w0.145: U11.35@109.886,70.165 109.886,69.467 112.586,66.767 114.948,66.767 115.248,66.467 118.786,66.467 121.486,69.167 R84.2@123.386,69.167
U11_36: R85.2 U11.36 | length 16.4
  Top Layer w0.145: U11.36@110.386,70.165 110.386,69.467 112.787,67.066 115.068,67.066 115.367,66.767 118.588,66.767 122.487,70.665 R85.2@123.386,70.665
U11_37: R86.2 U11.37 | length 16.4
  Top Layer w0.145: U11.37@110.887,70.166 110.887,69.467 112.975,67.379 115.174,67.379 115.487,67.066 118.387,67.066 123.386,72.065 R86.2@123.386,72.167
U11_38: R87.2 U11.38 | length 16.8
  Top Layer w0.145: U11.38@111.387,70.166 111.387,69.467 113.177,67.677 115.346,67.677 115.656,67.366 118.187,67.366 121.987,71.166 121.987,72.266 R87.2@123.386,73.665
U11_89: R83.2 U11.89 | length 1.9
  Top Layer w0.145: U11.89@110.887,85.366 110.887,86.666 R83.2@111.287,87.066
U11_90: BOOT.1 R83.1 U11.90 | length 7
  Top Layer w0.145: v1(108.987,87.066) R83.1@109.887,87.066 110.387,86.566 U11.90@110.387,85.366
  Bottom Layer w0.145: v1(108.987,87.066) BOOT.1@108.987,91.296
USB_AUX0_N: CN14.6 U2.8 U6.6 USB_AUX.6 | length 141.5
  Top Layer w0.145: v1(89.487,86.193) 89.087,85.966 82.985,85.966 77.984,80.965 74.588,80.965 73.887,80.267 73.887,78.992 75.311,77.564 88.07,77.564 98.888,66.746 98.888,59.967 100.47,58.385 U2.8@101.132,58.383 ; v1(91.687,88.966) 92.187,89.466 102.088,89.466 102.787,90.165 119.487,90.165 120.587,89.065 126.508,89.065 127.008,88.565 135.888,88.565 v1(136.337,88.916) 137.917,88.915 141.989,92.987 141.989,97.419 146.038,101.465 151.197,101.465 CN14.6@152.827,99.836 ; v1(135.687,83.266) 136.282,82.671 U6.6@136.759,82.671 U6.6@137.392,82.671
  Bottom Layer w0.145: v1(89.487,86.193) 91.687,88.395 v1(91.687,88.966) ; v1(135.687,83.266) 135.687,87.485 136.337,88.135 v1(136.337,88.916)
USB_AUX0_P: CN14.5 U2.9 U6.5 USB_AUX.7 | length 143.1
  Top Layer w0.145: USB_AUX.7@75.311,79.566 77.013,77.866 88.187,77.866 99.187,66.866 99.187,60.267 100.436,59.019 U2.9@101.132,59.018 ; USB_AUX.7@75.311,79.568 75.212,79.467 74.288,79.467 74.186,79.573 74.186,80.147 74.707,80.665 76.187,80.666 76.695,80.666 76.698,80.668 78.107,80.668 ; 78.108,80.668 83.104,85.667 89.087,85.666 v1(89.487,85.443) ; v1(92.287,88.466) 92.286,88.844 92.609,89.167 102.213,89.167 102.911,89.865 119.365,89.865 120.465,88.765 126.388,88.765 126.886,88.265 136.487,88.266 v1(136.987,88.366) 137.237,88.616 138.037,88.616 138.204,88.783 ; v1(135.687,81.866) 136.152,81.401 U6.5@136.759,81.401 ; 138.187,88.765 142.286,92.865 142.286,97.264 146.188,101.166 150.986,101.166 151.486,100.665 151.486,98.636 CN14.5@152.827,97.296
  Bottom Layer w0.145: v1(89.487,85.443) 90.087,86.043 90.087,86.374 92.179,88.466 v1(92.287,88.466) ; v1(135.687,81.866) 136.287,82.466 136.287,83.466 135.987,83.766 135.987,87.366 v1(136.987,88.366)
USB_AUX1_N: U2.6 U11.12 USB_AUX.2 | length 77.8
  Top Layer w0.145: USB_AUX.2@72.712,77.565 74.087,76.167 88.166,76.167 97.887,66.446 97.887,59.766 100.539,57.115 U2.6@101.132,57.113 ; v1(80.187,81.166) 80.387,80.966 88.987,80.966 v1(89.737,80.216) ; v1(97.337,78.516) 97.636,78.217 103.137,78.217 103.188,78.265 U11.12@103.787,78.266 U11.12@103.787,78.316
  Bottom Layer w0.145: USB_AUX.2@72.712,77.565 71.588,78.689 71.588,80.165 72.385,80.965 79.986,80.965 v1(80.187,81.166) ; v1@89.736,80.216 90.037,79.916 95.388,79.916 96.787,78.517 v1(97.337,78.516)
USB_AUX1_P: U2.7 U11.13 USB_AUX.3 | length 75.8
  Top Layer w0.145: USB_AUX.3@72.712,79.567 73.988,78.29 73.988,76.967 74.486,76.467 88.286,76.467 98.187,66.566 98.187,60.066 100.504,57.749 U2.7@101.132,57.748 ; v1(80.187,80.266) 80.587,80.665 88.786,80.665 89.188,80.267 89.188,79.667 v1(89.137,79.716) ; v1(97.337,77.716) 97.488,77.866 103.086,77.866 103.086,77.765 U11.13@103.787,77.765
  Bottom Layer w0.145: USB_AUX.3@72.712,79.567 73.811,80.666 79.787,80.666 v1(80.187,80.266) ; v1(89.137,79.716) 89.238,79.614 95.24,79.614 97.138,77.716 v1(97.337,77.716)
USB_NANO_N: U2.10 U3.6 UARDU.1 | length 9.2
  Top Layer w0.145: U2.10@101.132,59.653 101.811,59.642 104.803,56.65 107.806,56.65 108.294,56.161 U3.6@108.915,56.161
USB_NANO_P: U2.11 U3.5 UARDU.2 | length 9
  Top Layer w0.145: U2.11@101.132,60.288 103.564,60.289 106.422,57.431 U3.5@108.915,57.431
USB_RTU_N: GNSS.3 U2.4 USB1.2 | length 50.5
  Top Layer w0.145: GNSS.3@60.519,54.798 62.787,57.066 64.737,57.066 65.687,58.016 66.719,58.016 70.287,54.445 70.287,52.865 USB1.2@71.387,51.766 82.065,51.765 83.467,50.366 98.088,50.366 98.486,50.765 98.486,54.346 99.985,55.845 U2.4@101.132,55.843
  Top Layer w0.15: USB1.2@71.387,51.766 USB1.2@71.387,51.893
USB_RTU_P: GNSS.1 U2.5 USB1.3 | length 44.7
  Top Layer w0.145: GNSS.1@64.055,58.334 66.819,58.334 USB1.3@71.387,53.766 ; USB1.3@71.387,53.766 73.086,52.065 82.187,52.065 83.589,50.665 97.938,50.665 98.189,50.917 98.189,54.468 100.201,56.48 U2.5@101.132,56.478
USB_UP_N: CN2.2 CN13.6 U2.15 | length 58.1
  Top Layer w0.145: CN2.2@75.537,98.816 77.587,100.866 78.987,100.866 80.386,99.466 81.578,99.466 CN13.6@83.747,97.296 ; v1(83.087,75.466) 83.688,74.867 84.189,74.867 84.489,75.166 87.867,75.166 96.988,66.045 96.988,63.066 96.117,62.195 U2.15@95.442,62.193
  Bottom Layer w0.145: v1(83.087,75.466) 83.686,76.065 84.166,76.065 86.287,78.186 86.287,88.867 83.587,91.567 83.587,97.137 CN13.6@83.747,97.296
USB_UP_P: CN2.3 CN13.5 U2.16 | length 57.1
  Top Layer w0.145: CN2.3@78.037,102.316 80.517,99.836 CN13.5@83.747,99.836 ; v1(83.987,75.466) 87.986,75.466 97.288,66.165 97.288,62.769 96.078,61.559 U2.16@95.442,61.558
  Bottom Layer w0.145: CN13.5@83.747,99.836 84.887,98.697 84.887,96.866 83.887,95.865 83.887,91.686 86.587,88.986 86.587,78.067 v1(83.987,75.466)
USCL: J6.4 R4.2 U2.23 U14.6 | length 23.1
  Top Layer w0.145: R4.2@92.087,56.066 92.787,55.366 v1(92.887,55.366) ; J6.4@92.697,44.916 92.698,46.175 93.622,47.102 U14.6@95.286,47.102
  Top Layer w0.15: R4.2@92.087,56.066 93.686,56.065 94.735,57.115 U2.23@95.442,57.113
  Bottom Layer w0.145: J6.4@92.697,44.916 91.738,44.915 90.488,46.167 90.488,47.366 89.688,48.166 89.688,49.845 90.407,50.566 91.161,50.566 92.187,51.593 92.187,54.666 v1(92.887,55.366)
USDA: J6.3 R2.1 U2.27 U14.5 | length 20.5
  Top Layer w0.145: J6.3@90.157,44.916 90.158,45.166 91.087,45.166 94.293,48.372 U14.5@95.286,48.372 ; v1(91.587,51.766) 91.588,52.565 R2.1@92.087,53.066
  Top Layer w0.15: R2.1@92.087,53.066 92.388,53.365 92.586,53.365 93.795,54.575 U2.27@95.442,54.573
  Bottom Layer w0.145: J6.3@90.157,44.916 90.157,47.196 89.388,47.965 89.388,49.967 90.287,50.866 90.686,50.866 v1(91.587,51.766)
VBUS1: CN8.3 TO_PC.A4 TO_PC.A9 TO_PC.B4 TO_PC.B9 | length 51.4
  Top Layer w1.5: 195.187,125.866 195.787,125.266 v1(195.786,105.966) v1(195.786,104.165) ; CN8.3@198.857,99.066 199.286,99.065 200.988,100.767 200.988,102.466 199.088,104.366 v1(199.088,105.966) 199.088,125.293 199.987,126.166
  other v1: 199.087,104.066
VBUS2: CN9.3 CN10.3 DC/AUX.A4 DC/AUX.A9 DC/AUX.B4 DC/AUX.B9 | length 78.9
  Top Layer w1.5: 195.187,49.066 195.487,49.366 195.887,49.766 v1(195.887,51.334) v1(195.887,53.266) 194.288,54.966 194.288,57.366 195.487,58.565 CN10.3@196.317,58.566 195.888,58.565 194.587,59.866 194.587,62.366 196.487,64.266 196.487,77.366 194.587,79.266 194.587,80.836 CN9.3@196.317,82.566 ; 199.987,49.266 199.187,50.066 v1(199.187,51.366) v1(199.187,53.264) 200.988,55.065 200.987,61.766 ; 200.587,81.266 200.587,79.266 198.888,77.567 198.888,63.866 200.988,61.765
  Bottom Layer w0.6: CN9.3@196.317,82.566 197.617,81.266 v1(200.987,81.316)
  other v1: 200.387,80.966
WAS: CN5.3 OP1.1 R13.2 R58.1 WAS.4 | length 40.8
  Top Layer w0.145: v1(67.687,99.066) 68.787,99.066 ; 68.786,99.065 69.487,99.766 69.487,100.965 68.588,101.867 68.588,107.465 69.487,108.367 69.487,110.566 69.988,111.067 73.787,111.067 74.887,109.967 76.688,109.967 CN5.3@78.037,111.316 82.688,106.665 86.886,106.665 86.886,106.266 R13.2@86.787,106.366
  Bottom Layer w0.145: OP1.1@64.287,99.816 66.937,99.816 v1(67.687,99.066)
  Bottom Layer w0.5: WAS.4@62.436,98.567 62.888,98.567 63.422,99.101 64.138,99.817 OP1.1@64.287,99.816
WAS+: CN5.1 F5.2 R74.2 WAS.1 | length 36.8
  Top Layer w0.5: WAS.1@60.488,96.815 60.463,98.443 64.588,102.565 64.588,106.065 64.986,106.467 65.786,106.467 R74.2@65.987,106.666 ; R74.2@65.987,106.666 v1(65.987,107.566) ; v1(70.187,110.266) 70.487,110.566 71.487,110.566 73.387,110.566 74.587,109.366 76.487,109.366 CN5.1@78.037,107.816
  Top Layer w1: WAS.1@60.487,96.816 61.937,95.366 F5.2@68.787,95.366
  Bottom Layer w0.5: v1(65.987,107.566) 68.687,110.266 v1(70.187,110.266)
WAS_0V: CN5.4 J5.1 OP1.2 R5.2 R57.1 | length 32.7
  Top Layer w0.145: OP1.2@64.287,97.276 65.297,96.266 69.487,96.266 J5.1@71.487,94.266 ; OP1.2@64.287,97.276 65.487,98.476 65.487,101.115 65.088,101.516 65.088,102.946 65.088,103.066 65.088,105.865 65.187,105.966 66.488,105.966 66.687,106.166 66.688,106.317 66.688,108.166 68.786,110.267 ; R57.1@68.787,110.266 R5.2@68.787,111.666 69.087,111.366 75.487,111.366 CN5.4@75.537,111.316
WAS_N: C33.2 R5.1 R97.1 U1.9 U17.5 | length 205.2
  Top Layer w0.145: R5.1@68.786,113.066 69.188,112.667 78.568,112.667 79.388,111.846 79.388,110.467 82.787,107.066 88.486,107.066 v1(90.287,105.266) ; R5.1@68.787,113.066 R97.1@68.787,114.466 ; v1(89.287,88.466) 89.64,88.113 90.44,88.113 91.588,86.965 91.588,76.683 102.408,65.862 114.472,65.862 114.768,65.566 125.787,65.566 ; 124.14,65.566 125.287,65.566 v1(125.587,65.866) ; C33.2@127.186,49.766 128.339,50.917 U17.5@128.988,50.917 ; U17.5@128.988,50.917 129.536,50.917 129.636,50.917 130.087,50.467 130.087,50.191 ; 130.087,50.165 130.087,49.167 131.689,47.564 135.088,47.564 136.386,46.266 137.287,46.266 147.686,46.266 152.987,51.567 156.787,51.567 158.288,53.068 v1(158.287,53.466) ; v1(175.687,56.766) 175.987,57.066 177.386,57.066 177.887,57.567 177.887,67.165 178.786,68.064 178.786,68.867 178.288,69.365 176.688,69.365 175.987,70.066 175.987,71.986 U1.9@177.066,73.066
  Bottom Layer w0.145: v1(89.287,88.466) 89.287,88.765 89.787,89.266 90.188,89.266 91.186,90.267 91.186,95.466 90.587,96.065 90.587,98.466 90.988,98.867 90.988,104.567 v1(90.287,105.266) ; v1(125.587,65.866) 128.936,62.517 128.936,55.667 126.086,52.814 126.086,51.664 125.786,51.364 125.786,50.968 126.289,50.465 v1(127.987,50.466) ; v1(158.287,53.466) 162.088,53.467 164.087,51.468 164.087,50.785 165.405,49.467 172.187,49.467 172.888,48.766 174.587,48.766 176.487,50.665 176.487,54.067 175.687,54.867 v1(175.687,56.766)
WORK_1: R45.1 WORK.1 | length 8.5
  Top Layer w0.145: WORK.1@67.637,84.666 68.387,85.416 68.387,86.266 69.587,87.466 74.187,87.466 R45.1@74.387,87.666
pads on no net: CN6.6 CN6.7 CN6.8 CN6.11 CN6.12 CN16.1 DC/AUX. DC/AUX.A8 DC/AUX.B8 GNSS. INPUTS. P2. POWER. Q7.2 STEERING.@180.987,111.066 STEERING.@184.987,111.066 TO_PC. TO_PC.A8 TO_PC.B8 U1.5 U1.20 U1.25 U1.29 U1.33 U1.34 U1.35 U1.36 U1.37 U1.38 U1.39 U1.40 U2.25 U3.7 U3.8 U3.9 U3.10 U3.11 U3.12 U3.14 U3.15 U5.19 U6.7 U6.8 U6.9 U6.10 U6.11 U6.12 U6.13 U6.14 U10.4 U11.3 U11.4 U11.8 U11.15 U11.16 U11.17 U11.18 U11.23 U11.26 U11.27 U11.28 U11.29 U11.39 U11.40 U11.41 U11.42 U11.43 U11.44 U11.46 U11.52 U11.55 U11.56 U11.57 U11.59 U11.61 U11.62 U11.63 U11.64 U11.65 U11.66 U11.67 U11.68 U11.69 U11.70 U11.72 U11.73 U11.74 U11.77 U11.78 U11.80 U11.81 U11.82 U11.83 U11.84 U11.85 U11.86 U11.87 U11.88 U11.91 U11.92 U11.93 U11.94 U11.95 U11.97 U11.98 U11.100 U15. U15.4 U15.5 U17.2 U18.3 U18.8 U18.9 U18.11 U18.13 U18.15 U18.16

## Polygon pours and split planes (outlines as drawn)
MA on Bottom Layer (solid): 117.437,130.816 188.637,130.866 189.287,130.216 189.287,122.466 188.637,121.816 118.637,121.766
+MOTOR on Bottom Layer (solid): 53.587,116.616 53.587,128.566 55.387,130.366 55.837,130.816 117.287,130.816 118.537,121.566 144.687,121.566 144.737,99.316 143.187,97.766 122.187,97.766 115.287,104.666 114.887,105.066 114.887,115.216 105.587,124.516 74.237,124.516 66.287,116.566 62.137,116.566
+MOTOR on Bottom Layer (solid): 54.837,126.866 56.687,128.716 67.537,128.716 66.387,127.566 66.387,122.516 65.987,122.916 55.787,122.916 55.787,123.116
GND on Bottom Layer (solid): 53.637,112.166 63.737,112.216 64.137,112.616 64.687,113.866 65.387,114.666 72.187,122.466 100.187,122.466 112.487,110.166 112.487,102.416 117.537,97.366 142.987,97.366 144.887,99.216 144.887,121.516 185.637,121.516 189.137,116.566 189.137,42.716 188.537,42.116 54.637,42.116 53.787,42.966
GND2 on Bottom Layer (solid): 192.787,42.366 202.487,42.366 202.487,87.766 201.087,89.166 194.187,89.166 192.787,87.766 192.887,87.666
GND1 on Bottom Layer (solid): 192.687,132.866 201.787,132.866 202.487,132.166 202.487,94.066 201.087,92.666 194.287,92.666 192.787,94.166
GND1 on Top Layer (solid): 192.687,132.866 202.487,132.866 202.487,94.066 201.087,92.666 194.287,92.666 192.787,94.166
